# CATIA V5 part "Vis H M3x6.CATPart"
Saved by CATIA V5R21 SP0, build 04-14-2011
Part number: Vis H M3x6
Material "Acier": density 7860 kg/m3, Young's modulus 2e+11 Pa, Poisson ratio 0.266, thermal expansion 1.17e-05 1/K
Bounding box of the stored display mesh (mm): x -2.5 to 2.5, y -2.887 to 2.887, z 0 to 8
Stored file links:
  C:\Users\Olivier\Desktop\redaction CATIA (local)\CATIA\DONNEES\Exercice mise en plan 2 (Pompe de ventilation)\Pompe de ventilation (Product inclus)\Vis H M3x6.CATPart
  C:\Program Files\Dassault Systemes\B21\win_b64\startup\materials\French\Catalog.CATMaterial
  C:\Users\Olivier\Desktop\redaction CATIA (local)\CATIA\DONNEES\Exercice mise en plan 2 (Pompe de ventilation)\Pompe de ventilation (Product inclus)\CATIA_EnvironmentMap_Satin_512x512.jpg
  C:\Users\Olivier\Desktop\redaction CATIA (local)\pompe à moteur de ventilation refait\Pompe_a_moteur_de_ventilation.CATProduct
  C:\Users\Olivier\Desktop\redaction CATIA (local)\pompe à moteur de ventilation refait\Ecrou a collerette M5.CATPart
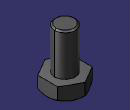
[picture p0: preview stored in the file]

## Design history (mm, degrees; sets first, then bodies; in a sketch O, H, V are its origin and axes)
Body1 (main body), material "Acier"
  Sketch1 on xy-plane, origin (0, 0, 0), H (1, 0, 0), V (0, 1, 0)
    circle A1 centre (0, 0) radius 1.5
    point P1 (2.5, -1.4434)
    point P2 (2.5, 1.4434)
    point P3 (0, 2.8868)
    point P4 (-2.5, 1.4434)
    point P5 (-2.5, -1.4434)
    point P6 (0, -2.8868)
    point P7 (2.5, 0)
    line L1 (2.5, -1.4434) -> (2.5, 1.4434)
    line L2 (2.5, 1.4434) -> (0, 2.8868)
    line L3 (0, 2.8868) -> (-2.5, 1.4434)
    line L4 (-2.5, 1.4434) -> (-2.5, -1.4434)
    line L5 (-2.5, -1.4434) -> (0, -2.8868)
    line L6 (0, -2.8868) -> (2.5, -1.4434)
    construction line L7 (0, 0) -> (2.5, 0)
    construction circle A2 centre (0, 0) radius 2.8868
    construction arc A3 centre (-2.5, -1.4434) radius 2.8868 from (-2.5, 1.4434) to (0, -2.8868) cw
    construction arc A4 centre (2.5, 1.4434) radius 2.8868 from (0, 2.8868) to (2.5, -1.4434) ccw
    distance L1 L4 = 5
    horizontal: L7 H
    coincidence: A2 P1, A2 P2, A2 P3, A2 P4, A2 P5, A2 P6, A3 O, A4 O
    midpoint: P7 L1
  MultiPad1: profile Sketch1, domains (length 2; length 8)
  Sketch2 on yz-plane, origin (0, 0, 0), H (0, 1, 0), V (0, 0, 1)
    line L1 (2.509, 0) -> (2.9319, 0.3605)
    point P1 (2.509, 0)
    line L2 (2.9319, 0.3605) -> (2.9319, 0)
    point P3 (2.9319, 0)
    line L3 (2.9319, 0) -> (2.509, 0)
    coincidence: P1 H, P3 H
    vertical: L2 V
    horizontal: L3 H
  Groove1: profile Sketch2, axis Sketch2.V, angle 360
  Chamfer1: length 0.2, angle 45, on face of MultiPad1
